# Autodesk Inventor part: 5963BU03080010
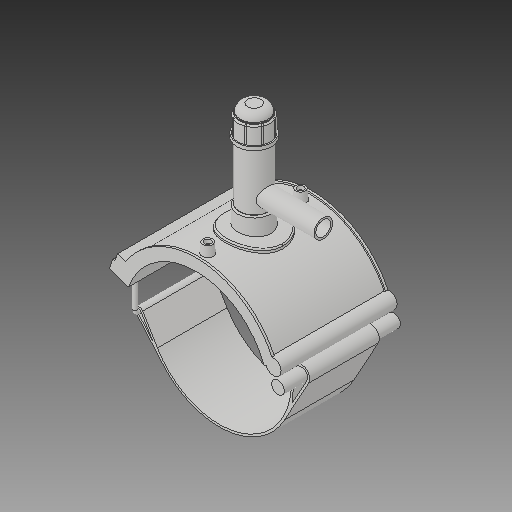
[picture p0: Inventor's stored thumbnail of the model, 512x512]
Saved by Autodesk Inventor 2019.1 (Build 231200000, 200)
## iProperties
Created: 2017-07
Part Number: 5963BU03080010
Material: Generic
Description: PLASSON TAPPING SADDLE 8''IPS x 1''CTS
Document SubType Name: Modeling
Designer: KIM
Mass: 1712.7 g
Surface Area: 2671.49 cm^2
Volume: 1712.7 cm^3
Density: 1 g/cm^3
Appearance: Default
Author: KIM
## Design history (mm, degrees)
derived "5963B.ipt"
feature "Solid1::5963B.ipt"
feature "Solid2::5963B.ipt"
feature "Solid4::5963B.ipt"
feature "Solid5::5963B.ipt"
tag "TaggingFeature1" dims "d0" = 218.7
body "Solid1"
body "Solid2"
other parameters: "d2" = 269.748, "d3" = 54.675, "d4" = 176.022, "d5" = 0, "d6" = 0.1, "d8" = 0, "d19" = 6, "d20" = 6, "d21" = 105.6132, "d23" = 0, "d24" = 52.8066, "d26" = 0, "d29" = 3, "d30" = 72.9, "d31" = 6, "d32" = 0, "d33" = 0, "d34" = 0.6, "d40" = 129.64536, "d41" = 87.48, "d43" = 0, "d45" = 0, "d47" = 230.2722, "d70" = 15, "d72" = 0, "d73" = 6, "d75" = 5, "d76" = 0, "d77" = 10.935, "d78" = 139.35, "d79" = 15, "d80" = 70.4088, "d82" = 5 deg, "d84" = 4, "d85" = 14, "d86" = 0, "d87" = 3, "d88" = 0, "d89" = 1, "d90" = 1, "d91" = 140.8176, "d92" = 0, "d93" = 0.5, "d94" = 115.10526, "d96" = 254.30436, "d97" = 3.52044, "d98" = 0, "d102" = 2.187, "d120" = 140 deg, "d121" = 24.228, "d122" = 20 deg, "d123" = 498.636, "d124" = 149.5908, "d126" = 0, "d143" = 225.261, "d145" = 23.55231, "d149" = 3.2805, "d150" = 25.90754, "d153" = 176.022, "d154" = 0, "d156" = 124.659, "d157" = 160 deg, "d159" = 6.1236, "d161" = 3.2805, "d162" = 105.6132, "d163" = 0, "d164" = 109.35, "d167" = 21.87, "d168" = 121.61854, "d170" = 3.2805, "d172" = 0, "d173" = 1, "d175" = 109.35, "d176" = 20 deg, "d177" = 15.309, "d178" = 30.618, "d180" = 0, "d183" = 12.2472, "d184" = 12.2472, "d185" = 57.20715, "d186" = 57.20715, "d187" = 124.659, "d188" = 9.1854, "d189" = 15.309, "d190" = 0, "d191" = 186.9885, "d193" = 6.1236, "d194" = 6.16077, "d195" = 90 deg, "d197" = 0, "d199" = 0, "d200" = 15.309, "d202" = 0, "d203" = 177.038, "d204" = 49.8636, "d205" = 36.7416, "d206" = 44.6148, "d207" = 132.7785, "d208" = 138.08964, "d209" = 164.64534, "d210" = 45.13968, "d211" = 52.488, "d212" = 41.9904, "d213" = 45.7191, "d216" = 0, "d217" = 21.87, "d218" = 10.935, "d219" = 2.187, "d222" = 218.7, "d224" = 0, "d230" = 2.187, "d233" = 6, "d236" = 89.916, "d237" = 52.8066, "d238" = 6.02433, "d240" = 52.8066, "d241" = 52.8066, "d242" = 52.8066, "d243" = 6, "d244" = 52.8066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
